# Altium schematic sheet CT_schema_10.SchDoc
size 277 x 170 mm
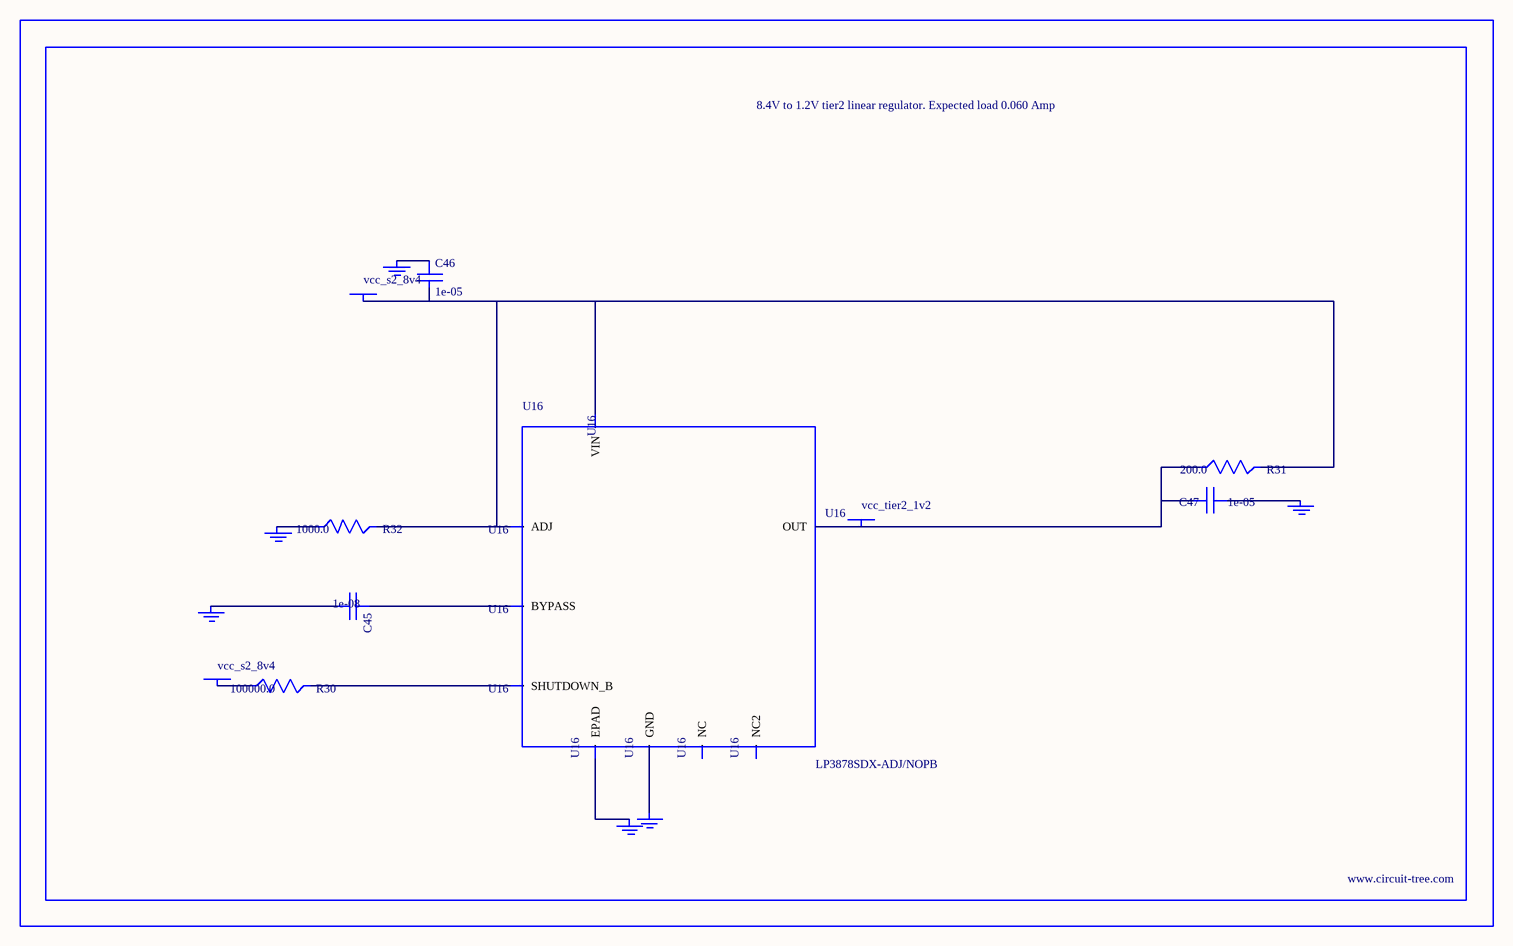
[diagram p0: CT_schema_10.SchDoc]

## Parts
BORDER9  (no value)
C45  1e-08  [C0402]
C46  1e-05  [C1206]
C47  1e-05  [C0805]
GND_INSTANCE_9_0  (no value)
GND_INSTANCE_9_1  (no value)
GND_INSTANCE_9_2  (no value)
GND_INSTANCE_9_3  (no value)
GND_INSTANCE_9_4  (no value)
GND_INSTANCE_9_5  (no value)
POWER_INSTANCE_9_0  vcc_s2_8v4
POWER_INSTANCE_9_1  vcc_s2_8v4
POWER_INSTANCE_9_2  vcc_tier2_1v2
R30  100000.0  [R0603]
R31  200.0  [R0603]
R32  1000.0  [R0603]
U16  LP3878SDX-ADJ/NOPB  [WSON-8]

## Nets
NetC45_1: C45.1 U16.1(BYPASS)
NetC45_2: C45.2 GND_INSTANCE_9_0.0(GND)
NetC46_1: C46.1 GND_INSTANCE_9_1.0(GND)
NetC46_2: C46.2 POWER_INSTANCE_9_0.0(PWR) R31.2 R32.2 U16.4(VIN) U16.6(ADJ)
NetC47_1: C47.1 GND_INSTANCE_9_2.0(GND)
NetC47_2: C47.2 POWER_INSTANCE_9_2.0(PWR) R31.1 U16.5(OUT)
NetGND_INSTANCE_9_3_0: GND_INSTANCE_9_3.0(GND) R32.1
NetGND_INSTANCE_9_4_0: GND_INSTANCE_9_4.0(GND) U16.PAD(EPAD)
NetGND_INSTANCE_9_5_0: GND_INSTANCE_9_5.0(GND) U16.3(GND)
NetPOWER_INSTANCE_9_1_0: POWER_INSTANCE_9_1.0(PWR) R30.1
NetR30_2: R30.2 U16.8(SHUTDOWN_B)

Not connected (* = marked no-connect by the designer): U16 2(NC) 7(NC2)

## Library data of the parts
BORDER9 = BORDER_PAGE9
C45 = C0402C103K3RAC
C46 = C1206C106K3RACTU
C47 = GRM219R60J106ME19D
GND_INSTANCE_9_0-GND_INSTANCE_9_5 = GND
POWER_INSTANCE_9_0-POWER_INSTANCE_9_2 = PWR
R30 = RC0603JR-07100KL
R31 = RC0603JR-07200RL
R32 = RC0603JR-071KL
